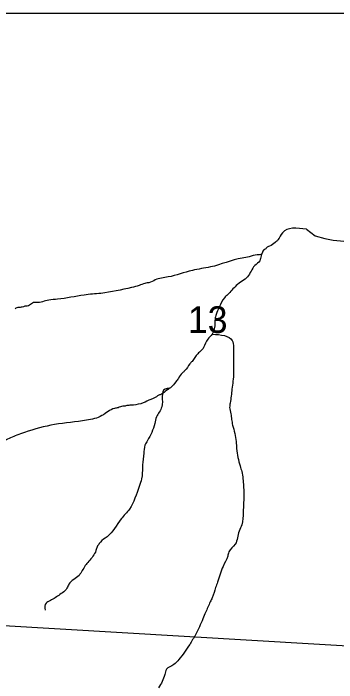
# Model space of a CAD drawing. Extents: x -13.1 to 43.1, y 0 to 22.
# Drawn here: x 6.242 to 6.749, y 19.849 to 20.9 of the extents above; entities that cross this region are included whole.
import ezdxf

# ---------------------------------------------------------------- set-up
doc = ezdxf.new("R2010")
doc.units = 0
for name, color, linetype in [('GM_X_Corporation', 7, 'Continuous'), ('GM_X_Minor_River', 7, 'Continuous'), ('GM_X_Section_Text', 7, 'Continuous')]:
    doc.layers.add(name, color=color, linetype=linetype)

msp = doc.modelspace()

# ---------------------------------------------------------------- linework, layer by layer
at = {"layer": 'GM_X_Corporation'}
for points in [[(7.0807, 20.9), (2.1, 20.9), (2.1, 14.1), (6.6193, 14.1), (6.6994, 15.2069), (6.7531, 15.956), (6.8236, 16.9075), (6.9509, 19.0179), (7.0108, 19.8446), (7.0164, 19.8954), (7.0617, 20.6133)], [(7.0804, 20.9), (2.1, 20.9), (2.1, 14.1), (6.619, 14.1), (6.6992, 15.2074), (6.7528, 15.9566), (6.8234, 16.908), (6.8365, 17.1257), (6.9507, 19.0184), (6.9616, 19.1692), (7.0106, 19.8452), (7.0162, 19.896), (7.0615, 20.6138)], [(7.0804, 20.9), (2.1, 20.9), (2.1, 17.2152), (2.1437, 17.2135), (2.8442, 17.1637), (3.8328, 17.0966), (4.4304, 17.0575), (6.8234, 16.908), (6.8365, 17.1257), (6.9507, 19.0184), (6.9616, 19.1692), (7.0106, 19.8452), (7.0162, 19.896), (7.0615, 20.6138)], [(7.0765, 20.9), (6.0839, 20.9), (6.0143, 19.9509), (7.0143, 19.8917), (7.0727, 20.8375)]]:
    msp.add_lwpolyline(points, close=True, dxfattribs=at)
at = {"layer": 'GM_X_Minor_River'}
msp.add_lwpolyline([(6.7023, 20.5611), (6.7158, 20.5506), (6.7306, 20.5466), (6.744, 20.5439), (6.7723, 20.5412)], dxfattribs=at)
for points in [[(6.7023, 20.5611), (6.6642, 20.5552), (6.6573, 20.5443), (6.6531, 20.5402), (6.644, 20.5343), (6.6406, 20.5329), (6.6372, 20.5295), (6.6345, 20.528), (6.6315, 20.522), (6.6247, 20.5206), (6.6122, 20.5178), (6.6012, 20.5157), (6.5513, 20.5016), (6.523, 20.4963), (6.4848, 20.4859), (6.4647, 20.4813), (6.4549, 20.4769), (6.4519, 20.4766), (6.4485, 20.4759), (6.4394, 20.4726), (6.4276, 20.4693), (6.3793, 20.4602), (6.3532, 20.4576), (6.3116, 20.451), (6.2976, 20.4496), (6.278, 20.4458), (6.2738, 20.4458), (6.2704, 20.4436), (6.264, 20.4403), (6.2602, 20.44), (6.256, 20.4385), (6.253, 20.4382), (6.2477, 20.4375), (6.2447, 20.4357)], [(6.6313, 20.522), (6.6307, 20.519), (6.6288, 20.5115), (6.6208, 20.5037), (6.6097, 20.4864), (6.601, 20.4794), (6.5919, 20.4723), (6.5782, 20.4581), (6.5732, 20.4533), (6.5652, 20.4387), (6.5602, 20.427), (6.5587, 20.4198), (6.5583, 20.4142), (6.554, 20.3961), (6.5471, 20.3882), (6.5406, 20.3751), (6.5364, 20.3699), (6.5315, 20.3654), (6.5227, 20.3534), (6.5189, 20.3493), (6.5113, 20.3388), (6.5075, 20.3355), (6.501, 20.3265), (6.4972, 20.3213), (6.4885, 20.3119), (6.4839, 20.3086), (6.4744, 20.3019), (6.4703, 20.3001), (6.4627, 20.2953), (6.4578, 20.2935), (6.4456, 20.288), (6.4305, 20.2848), (6.4264, 20.2845), (6.4203, 20.2838), (6.4173, 20.2831), (6.4139, 20.2828), (6.4063, 20.2806), (6.401, 20.2795), (6.381, 20.2681), (6.3571, 20.2609), (6.3069, 20.254), (6.2596, 20.2418), (6.2475, 20.2375), (6.2285, 20.2287), (6.2236, 20.2257), (6.2134, 20.2175), (6.2077, 20.2127), (6.1933, 20.2031), (6.1838, 20.1991), (6.1656, 20.1906), (6.155, 20.1859), (6.152, 20.1814), (6.1379, 20.1717), (6.133, 20.1699), (6.1251, 20.1662), (6.1179, 20.1622), (6.1136, 20.1524)], [(6.554, 20.3961), (6.5856, 20.3862), (6.5873, 20.3627), (6.5876, 20.3491), (6.5867, 20.3223), (6.5851, 20.3098), (6.5823, 20.2879), (6.5815, 20.2811), (6.5833, 20.2709), (6.5844, 20.2622), (6.5862, 20.2531), (6.5917, 20.2273), (6.5924, 20.2163), (6.5979, 20.189), (6.6004, 20.1803), (6.6033, 20.1576), (6.6036, 20.147), (6.6031, 20.1254), (6.6026, 20.1163), (6.6006, 20.0967), (6.5964, 20.0866), (6.5902, 20.0662), (6.5803, 20.0539), (6.5784, 20.0471), (6.5711, 20.0313), (6.5626, 20.0065), (6.5595, 19.9982), (6.5541, 19.982), (6.5511, 19.9757), (6.5438, 19.9591), (6.5396, 19.949), (6.5277, 19.9238), (6.5189, 19.9088), (6.5017, 19.8849), (6.4938, 19.877), (6.4824, 19.8696), (6.4797, 19.8614), (6.4701, 19.8407)], [(6.4873, 20.3111), (6.4801, 20.3098), (6.475, 20.2819), (6.4666, 20.2661), (6.4639, 20.2556), (6.4524, 20.2289), (6.4486, 20.2218), (6.4466, 20.2082), (6.4462, 20.2033), (6.445, 20.1938), (6.4446, 20.187), (6.4433, 20.1689), (6.4395, 20.1569), (6.4241, 20.1212), (6.4112, 20.1058), (6.3891, 20.0778), (6.3788, 20.0696), (6.3769, 20.067), (6.3735, 20.0621), (6.3716, 20.0561), (6.3605, 20.0393), (6.3548, 20.0325), (6.3452, 20.0172), (6.3293, 20.0034), (6.3262, 19.997), (6.319, 19.9899), (6.3114, 19.9844), (6.2963, 19.9755), (6.2936, 19.9737), (6.292, 19.9627)]]:
    msp.add_spline(points, degree=3, dxfattribs=at)

# ---------------------------------------------------------------- texts
at = {"layer": 'GM_X_Section_Text'}
msp.add_text('13', height=0.04186, rotation=0, dxfattribs=at).set_placement((6.5159, 20.398))

doc.saveas('drawing.dxf')
